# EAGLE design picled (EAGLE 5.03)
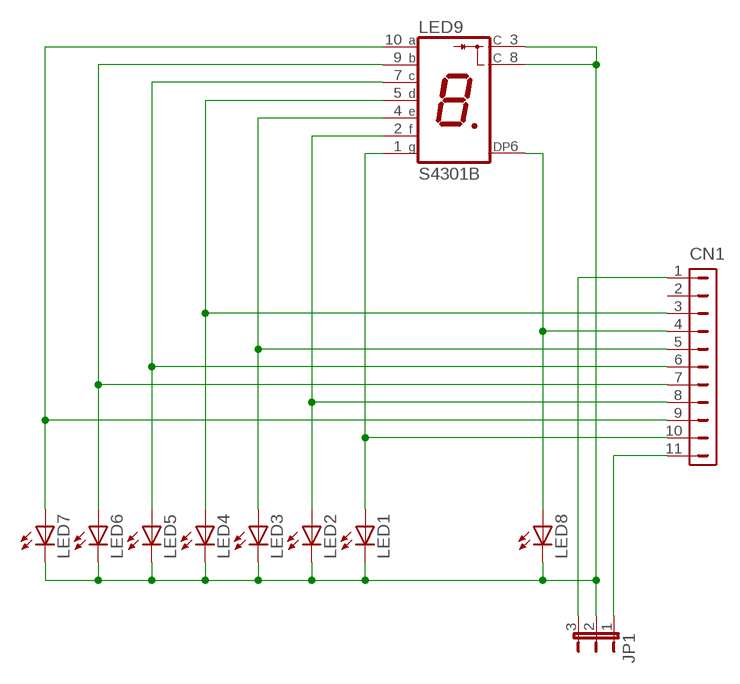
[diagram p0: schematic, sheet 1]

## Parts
CN1  HDR-1X11-SIP-100  [SIP-100-11V]
JP1  JP2E  [JP2]
LED1  LED5MM  [LED5MM]
LED2  LED5MM  [LED5MM]
LED3  LED5MM  [LED5MM]
LED4  LED5MM  [LED5MM]
LED5  LED5MM  [LED5MM]
LED6  LED5MM  [LED5MM]
LED7  LED5MM  [LED5MM]
LED8  LED5MM  [LED5MM]
LED9  S4301B  [S4301B]

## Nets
N$1: CN1.10 LED1.A LED9.1(G)
N$2: CN1.5 LED3.A LED9.4(E)
N$3: CN1.1 JP1.3
N$4: CN1.6 LED5.A LED9.7(C)
N$5: CN1.9 LED7.A LED9.10(A)
N$6: CN1.4 LED8.A LED9.6(DP)
N$7: CN1.7 LED6.A LED9.9(B)
N$8: CN1.3 LED4.A LED9.5(D)
N$9: CN1.8 LED2.A LED9.2(F)
N$10: CN1.11 JP1.1
N$16: JP1.2 LED1.K(C) LED2.K(C) LED3.K(C) LED4.K(C) LED5.K(C) LED6.K(C) LED7.K(C) LED8.K(C) LED9.3(C) LED9.8(C)
Unconnected: CN1.2

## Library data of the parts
CN1 = con-hdrs40:HDR-1X11: HEADER CONNECTOR
JP1 = jumper:JP2E: JUMPER
LED1-LED8 = led:LED: LED
LED9 = led-7-segment:S4301B: Single Digit Seven-Segment Display (cathode common) Source: LITEON .. S4301B.pdf

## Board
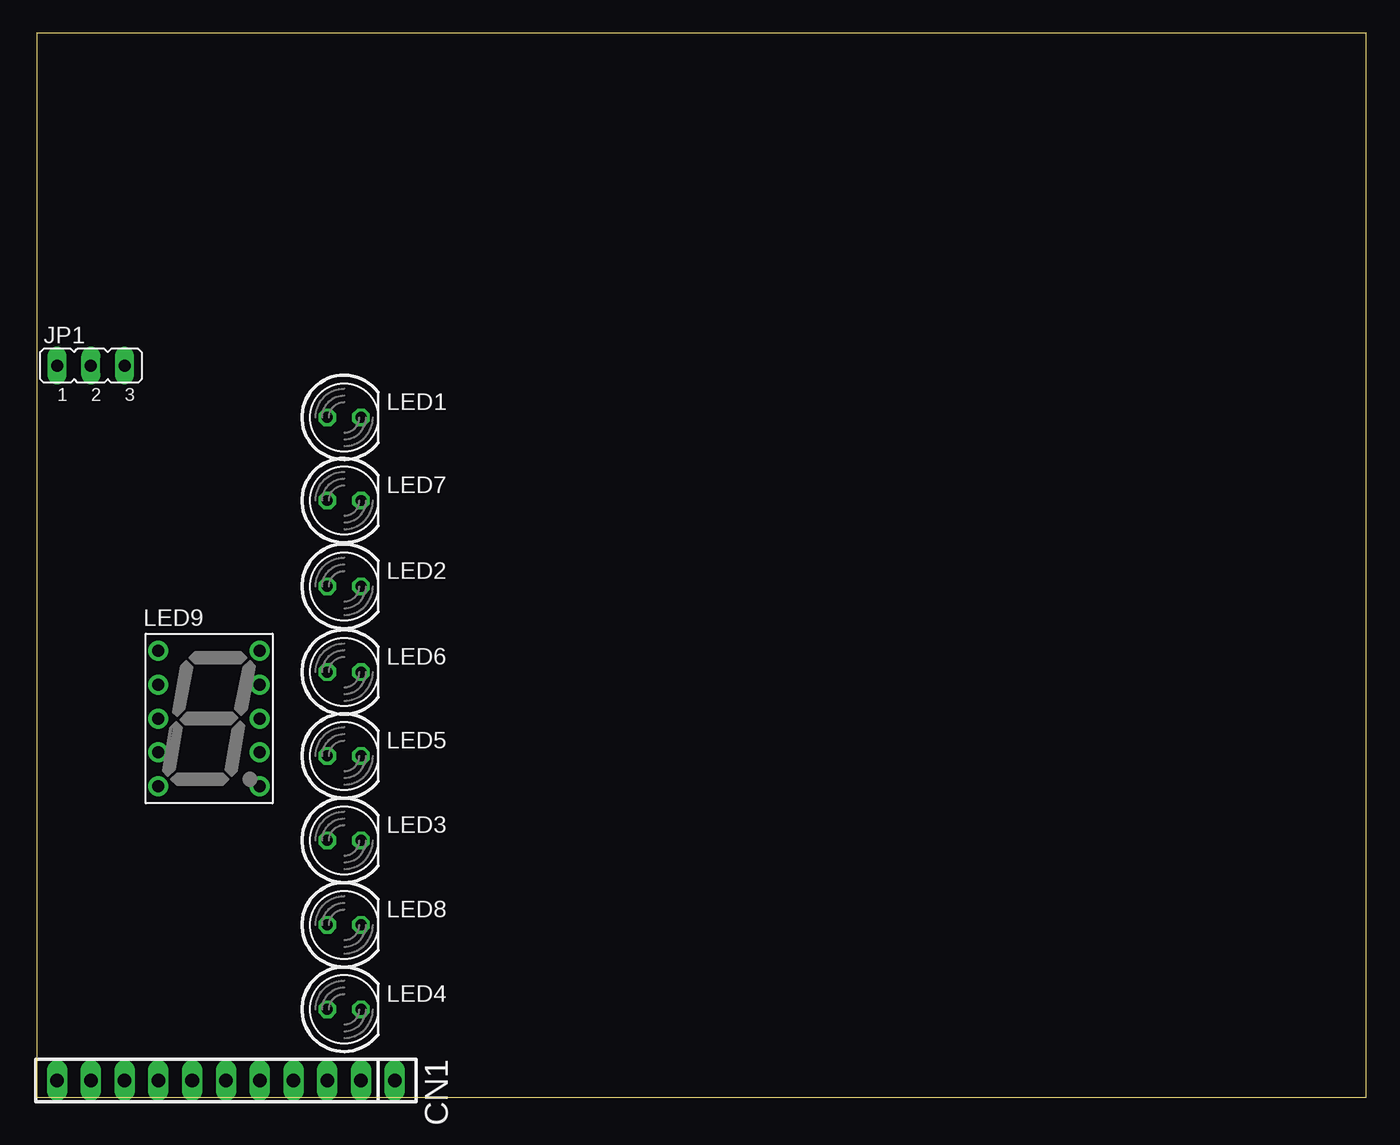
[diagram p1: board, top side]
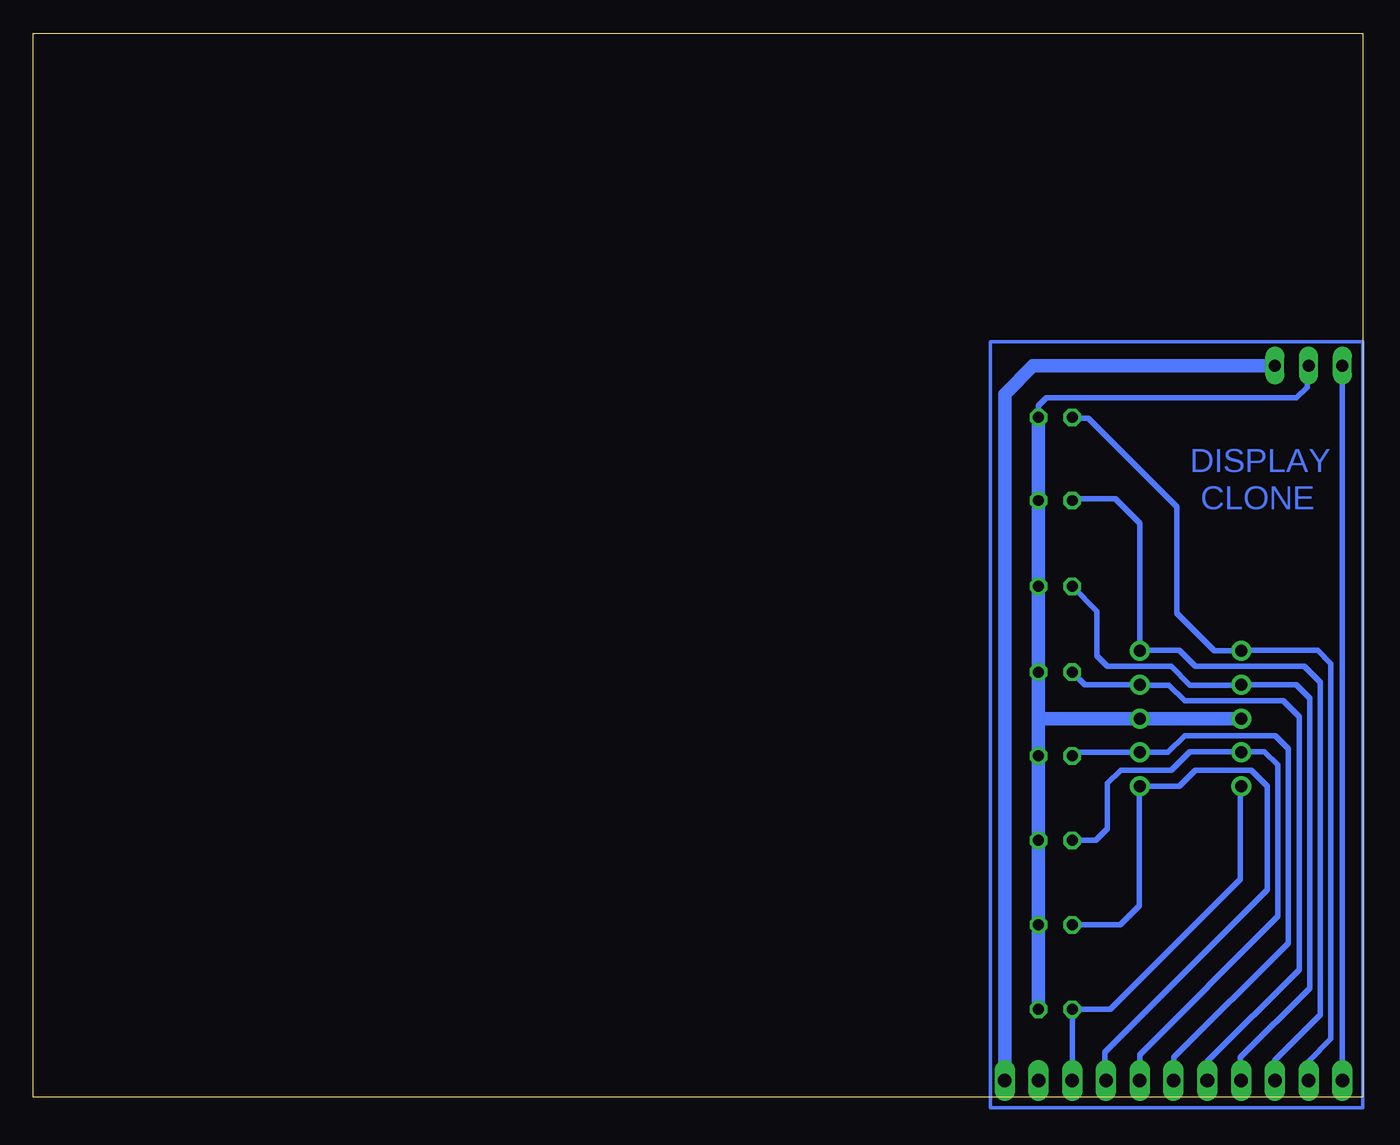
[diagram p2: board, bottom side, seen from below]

Size 100 x 80 mm. Coordinates in mm from the lower left corner, seen from the top.
Outline: 0,0 100,0 100,80 0,80 0,0
Copper layers (1*16): Top 0.035mm / dielectric 1.5mm / Bottom 0.035mm
Design rules "default": minimum track width 10mil, minimum drill 24mil, track to track 8mil, track to pad 8mil, pad to pad 8mil, via to via 8mil, smd to smd 8mil, copper to edge 40mil, drill to drill 8mil, minimum pad ring 10mil, minimum via ring 8mil, stop-mask expansion 4mil, vias tented up to drill 0mil, thermal gap 10mil

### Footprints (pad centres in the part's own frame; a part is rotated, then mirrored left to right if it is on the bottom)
SIP-100-11V = drill 1.016 long: 1 -12.7,0; 2 -10.16,0; 3 -7.62,0; 4 -5.08,0; 5 -2.54,0; 6 0,0; 7 2.54,0; 8 5.08,0; 9 7.62,0; 10 10.16,0; 11 12.7,0
JP2 = drill 0.914 long: 1 -2.54,0; 2 0,0; 3 2.54,0
LED5MM = drill 0.813 octagon: A -1.27,0; K 1.27,0
S4301B = drill 0.9 pad 1.5 round: 1 -3.81,5.08; 2 -3.81,2.54; 3 -3.81,0; 4 -3.81,-2.54; 5 -3.81,-5.08; 6 3.81,-5.08; 7 3.81,-2.54; 8 3.81,0; 9 3.81,2.54; 10 3.81,5.08

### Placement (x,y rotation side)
CN1  14.24,1.27 180 top
JP1  4.08,55.01 0 top
LED1  23.13,51.12 0 top
LED2  23.13,38.42 0 top
LED3  23.13,19.32 0 top
LED4  23.13,6.62 0 top
LED5  23.13,25.67 0 top
LED6  23.13,31.97 0 top
LED7  23.13,44.87 0 top
LED8  23.13,12.97 0 top
LED9  12.97,28.48 0 top

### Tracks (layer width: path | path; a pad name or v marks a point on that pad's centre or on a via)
N$1
  Bottom 0.406: CN1.10 4.08,2.72 2.4,4.4 2.4,32.6 3.4,33.6 9.12,33.6 LED9.1 11.16,33.56 14,36.4 14,41.4 | 14,41.4 14,42.4 | LED1.A 21.8,51.06 20.66,51.06 14,44.4 14,41.4
N$2
  Bottom 0.406: CN1.5 16.78,3.22 6.5,13.5 6.4,13.6 6.4,25 7.4,26 9.1,26 LED9.4 9.22,26 13,26 14.4,24.6 18.2,24.6 19.2,23.6 19.2,20.2 20.08,19.32 LED3.A
N$3
  Bottom 1.016: CN1.1 26.94,52.86 24.8,55 JP1.3
N$4
  Bottom 0.406: CN1.6 14.2,1.31 14.2,3 5.6,11.6 5.6,26.2 6.6,27.2 13.4,27.2 14.66,25.94 LED9.7 21.59,25.94 LED5.A
N$5
  Bottom 0.406: CN1.9 6.62,2.78 3.2,6.2 3.2,31.2 4.4,32.4 12.6,32.4 13.8,33.6 16.74,33.6 LED9.10 16.78,43.18 18.6,45 21.73,45 LED7.A
N$6
  Bottom 0.406: CN1.4 19.4,1.35 19.4,3.4 7.2,15.6 7.2,23.4 8.4,24.6 12.6,24.6 13.8,23.4 LED9.6 16.8,23.38 16.8,14.4 18.23,12.97 LED8.A
N$7
  Bottom 0.406: CN1.7 11.7,2.7 4.8,9.6 4.8,28.6 6,29.8 13.4,29.8 14.6,31 16.76,31 LED9.9 20.91,31.02 LED6.A
N$8
  Bottom 0.406: CN1.3 LED4.A 18.98,6.62 9.2,16.4 9.2,23.36 LED9.5
N$9
  Bottom 0.406: CN1.8 9.2,1.31 9.2,3 4,8.2 4,30 5.02,31.02 LED9.2 9.18,31 13,31 14.4,32.4 19.2,32.4 20,33.2 20,36.56 LED2.A
N$10
  Bottom 0.406: CN1.11 JP1.1
N$11
  Bottom 0.254: 0,56.8 28,56.8 28,-0.8 0,-0.8 0,56.8
N$16
  Bottom 0.406: LED1.K 24.4,52 23.8,52.6 5,52.6 4.2,53.4 4.2,54.89 JP1.2
  Bottom 1.016: LED4.K LED8.K LED3.K LED5.K 24.4,28.6 | 24.4,28.6 LED6.K LED2.K LED7.K LED1.K | LED9.3 LED9.8 24.28,28.48 24.4,28.6

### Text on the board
Bottom: DISPLAY | CLONE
